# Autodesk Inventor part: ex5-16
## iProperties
Shininess: 64.0
Length Units: 11272
Angle Units: 11279
Time Units: 11290
Mass Units: 11286
Length Display Precision: 3
Angle Display Precision: 2
Compacted: True
Part Number: ex5-16
Document SubType Name: Modeling
Created: 2002-09
Designer: Elise Moss
Density: 0.0
Volumn: 0.0
Area: 0.0
PropertySet Name: Model Information
Control State: 0
Master: False
Checked Out: False
Author: Elise Moss
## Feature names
1. Revolution1
2. Hole1
3. Circular Pattern1
